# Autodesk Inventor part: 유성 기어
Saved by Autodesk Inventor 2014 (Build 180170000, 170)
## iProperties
Created: 2026-05
Part Number: 유성 기어
Material: 일반
Document SubType Name: Modeling
Designer: dg
Density: 1 g/cm^3
Appearance: 기본값
Author: dg
Author: jhkim
Creation Date: 2026-04-27
Sending System: Autodesk Inventor 2027
Preprocessor: ST-DEVELOPER v20.1
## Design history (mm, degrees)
node "유성 기어1"
node "솔리드1"
node "기준1"
